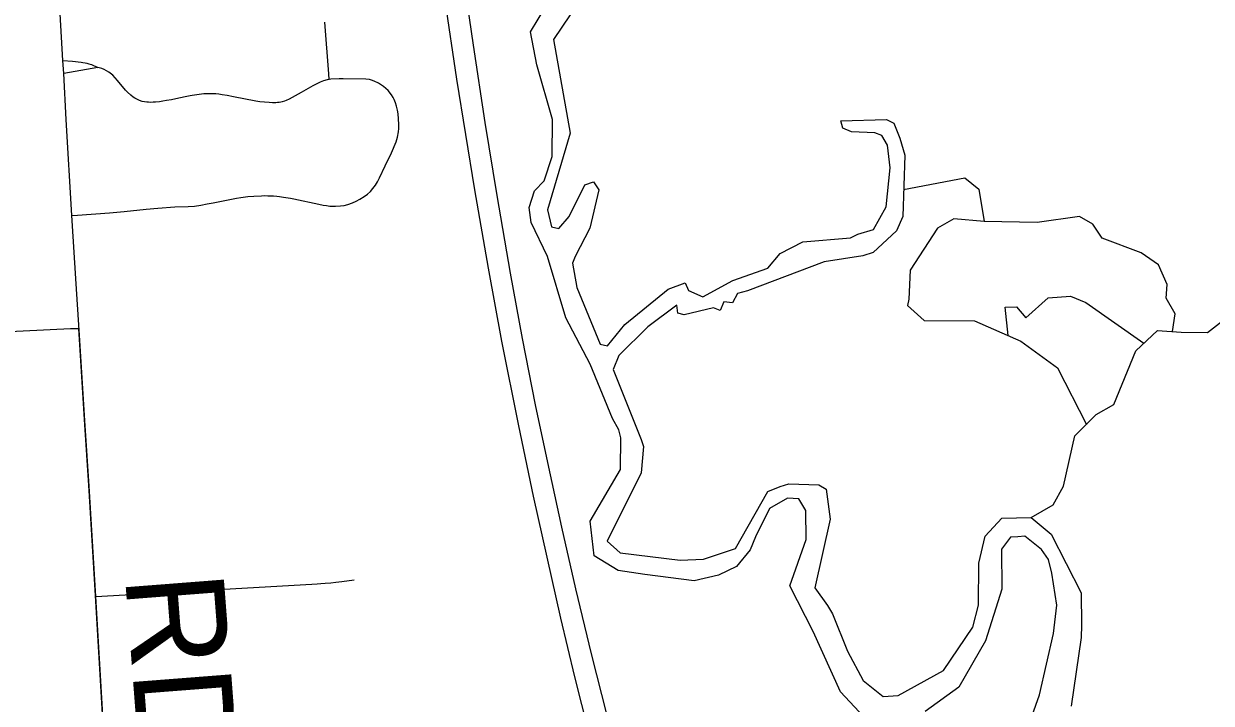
# Model space of a CAD drawing. Extents: x -6.4 to 34, y -4.2 to 22.
# Drawn here: x 3.688 to 4.373, y 19.407 to 19.8 of the extents above; entities that cross this region are included whole.
import ezdxf

# ---------------------------------------------------------------- set-up
doc = ezdxf.new("R2010")
doc.units = 0
for name, color, linetype in [('GM_X_Corporation', 7, 'Continuous'), ('GM_X_County_Road', 7, 'Continuous'), ('GM_X_County_Road_Text', 7, 'Continuous'), ('GM_X_Major_River', 7, 'Continuous'), ('GM_X_Minor_River', 7, 'Continuous'), ('GM_X_State_Route', 7, 'Continuous'), ('GM_X_Township_Road', 7, 'Continuous')]:
    doc.layers.add(name, color=color, linetype=linetype)

msp = doc.modelspace()

# ---------------------------------------------------------------- linework, layer by layer
at = {"layer": 'GM_X_Corporation'}
msp.add_lwpolyline([(3.73708, 19.33266), (3.72894, 19.4696), (3.7251, 19.53337), (3.72278, 19.56814), (3.71932, 19.62364), (3.7145, 19.62355), (3.65582, 19.62064)], dxfattribs=at)
at = {"layer": 'GM_X_County_Road'}
for points in [[(3.71955, 19.62276), (3.7178, 19.64956), (3.71545, 19.68905), (3.71217, 19.74445), (3.71066, 19.77108), (3.71023, 19.77858), (3.70647, 19.8427), (3.70137, 19.92977), (3.69885, 19.97289)], [(3.73728, 19.33211), (3.72914, 19.46905), (3.7253, 19.53281), (3.72298, 19.56759), (3.71955, 19.62276)]]:
    msp.add_lwpolyline(points, dxfattribs=at)
at = {"layer": 'GM_X_Major_River'}
for points in [[(4.17787, 19.39383), (4.15898, 19.41397), (4.14323, 19.44896), (4.1299, 19.47528), (4.13926, 19.50201), (4.13897, 19.5187), (4.13507, 19.52545), (4.12853, 19.52594), (4.11814, 19.51983), (4.10992, 19.50346), (4.10684, 19.4961), (4.09907, 19.48647), (4.08857, 19.48135), (4.07463, 19.47806), (4.04604, 19.48178), (4.03065, 19.48408), (4.01688, 19.49255), (4.01463, 19.51262), (4.03211, 19.54242), (4.03232, 19.56075), (4.0311, 19.56528), (4.02746, 19.57184), (4.01454, 19.60329), (4.00045, 19.62997), (3.98999, 19.66544), (3.98057, 19.685), (3.97928, 19.6937), (3.98251, 19.70325), (3.98802, 19.70898), (3.99265, 19.72319), (3.99275, 19.74441), (3.98387, 19.77612), (3.98013, 19.79501), (3.99335, 19.81726)], [(4.00303, 19.80492), (3.99344, 19.79071), (4.0031, 19.73663), (3.98989, 19.69238), (3.99234, 19.68256), (3.99651, 19.6815), (4.00244, 19.68844), (4.01157, 19.70681), (4.01646, 19.70842), (4.01957, 19.70393), (4.01429, 19.68182), (4.00588, 19.66535), (4.00443, 19.66154), (4.00695, 19.64754), (4.02039, 19.61478), (4.02457, 19.61372), (4.03456, 19.62605), (4.05954, 19.64661), (4.06931, 19.65021), (4.07128, 19.64569), (4.07967, 19.64205), (4.0969, 19.65147), (4.1172, 19.65867), (4.12424, 19.66715), (4.13736, 19.67384), (4.16493, 19.67624), (4.16905, 19.67822), (4.17808, 19.68104), (4.18541, 19.69407), (4.18766, 19.7165), (4.18629, 19.72975), (4.18296, 19.73517), (4.17898, 19.73683), (4.16536, 19.73733), (4.1604, 19.73952), (4.15919, 19.74367), (4.18565, 19.74454), (4.18985, 19.74234), (4.19341, 19.73368), (4.19623, 19.72386), (4.19497, 19.68856), (4.19133, 19.68014), (4.17793, 19.66776), (4.17192, 19.66575), (4.14966, 19.6623), (4.10533, 19.64556), (4.09968, 19.64393), (4.09675, 19.63857), (4.09182, 19.63924), (4.08964, 19.63426), (4.08583, 19.63571), (4.06889, 19.63161), (4.06508, 19.63268), (4.06463, 19.63722), (4.04782, 19.62477), (4.0311, 19.60815), (4.02784, 19.60012), (4.04406, 19.55982), (4.04527, 19.55567), (4.04402, 19.54047), (4.02429, 19.50103), (4.03198, 19.49435), (4.06647, 19.49005), (4.08008, 19.49068), (4.09851, 19.49671), (4.11721, 19.52968), (4.12427, 19.53257), (4.12924, 19.53407), (4.14665, 19.53363), (4.15085, 19.53105), (4.15305, 19.51364), (4.1443, 19.47402), (4.15166, 19.46392), (4.1544, 19.45903), (4.16308, 19.43753), (4.1721, 19.42066), (4.18361, 19.41139)], [(4.18361, 19.41139), (4.1923, 19.41193), (4.21852, 19.42644), (4.23548, 19.45142), (4.23866, 19.464), (4.23898, 19.48828), (4.24249, 19.5039), (4.25214, 19.51433), (4.26915, 19.51464), (4.28067, 19.50498), (4.29791, 19.47115), (4.29817, 19.45257), (4.29799, 19.44536), (4.29226, 19.4058)], [(4.26246, 19.37983), (4.27399, 19.41229), (4.28207, 19.44772), (4.28404, 19.46407), (4.28107, 19.48261), (4.27914, 19.49048), (4.27512, 19.49628), (4.26556, 19.50395), (4.26141, 19.50349), (4.25725, 19.50342), (4.25208, 19.49649), (4.25211, 19.47335), (4.2428, 19.44358), (4.22739, 19.41674), (4.20797, 19.40273)]]:
    msp.add_lwpolyline(points, dxfattribs=at)
at = {"layer": 'GM_X_Minor_River'}
for points in [[(4.19552, 19.70407), (4.23088, 19.71084), (4.23894, 19.70416), (4.24192, 19.68562)], [(4.35073, 19.62203), (4.35218, 19.63226), (4.3471, 19.64127), (4.34772, 19.64925), (4.3426, 19.66054), (4.33264, 19.66756), (4.31018, 19.67588), (4.30473, 19.68412), (4.29709, 19.68854), (4.27257, 19.68505), (4.24192, 19.68562), (4.22449, 19.6872), (4.21513, 19.68172), (4.1993, 19.65752), (4.19846, 19.64082), (4.19777, 19.63701), (4.20738, 19.62846), (4.23651, 19.62824), (4.26319, 19.61658), (4.28427, 19.60104), (4.30103, 19.56844)], [(4.25592, 19.61976), (4.25414, 19.63615), (4.26057, 19.63626), (4.26598, 19.62992), (4.27901, 19.64154), (4.29186, 19.64253), (4.30062, 19.6389), (4.33424, 19.61534)], [(4.26915, 19.51464), (4.28188, 19.52208), (4.28775, 19.53281), (4.29442, 19.56177), (4.30668, 19.57413), (4.31679, 19.58001), (4.32948, 19.61098), (4.34214, 19.62259), (4.35577, 19.6217), (4.3709, 19.6216), (4.38477, 19.6323)]]:
    msp.add_lwpolyline(points, dxfattribs=at)
at = {"layer": 'GM_X_State_Route'}
for points in [[(3.88913, 20.13155), (3.89309, 20.10206), (3.90737, 19.99262), (3.91498, 19.93476), (3.92487, 19.85634), (3.93071, 19.81323), (3.93741, 19.76774), (3.94788, 19.70395), (3.95568, 19.65863), (3.96348, 19.61647), (3.97313, 19.56769), (3.98159, 19.52692), (3.99743, 19.4566), (4.00556, 19.42276), (4.02598, 19.34202), (4.03943, 19.29261)], [(3.94128, 19.82703), (3.94701, 19.78738), (3.95372, 19.7428), (3.96077, 19.70068), (3.96847, 19.65577), (3.97535, 19.6181), (3.9829, 19.57977), (3.98994, 19.54653), (3.99798, 19.50903), (4.00602, 19.47349), (4.0152, 19.43598), (4.02422, 19.40044), (4.03536, 19.35784), (4.0441, 19.326), (4.05333, 19.29269)]]:
    msp.add_lwpolyline(points, dxfattribs=at)
at = {"layer": 'GM_X_Township_Road'}
for points in [[(3.86384, 19.76755), (3.86362, 19.77079), (3.86134, 19.80062)], [(3.71023, 19.77858), (3.7157, 19.77806), (3.7207, 19.77751), (3.72178, 19.77738), (3.72306, 19.77716), (3.72408, 19.77693), (3.72526, 19.77662), (3.72596, 19.77639), (3.72664, 19.77614), (3.73028, 19.77458)], [(3.71545, 19.68905), (3.71871, 19.68923), (3.73716, 19.69052), (3.74565, 19.69131), (3.75833, 19.69274), (3.76503, 19.69332), (3.77489, 19.69399), (3.78257, 19.69425), (3.78622, 19.6945), (3.78986, 19.69497), (3.79357, 19.69572), (3.79688, 19.69635), (3.81048, 19.69904), (3.81295, 19.69945), (3.81687, 19.69999), (3.82048, 19.70031), (3.82476, 19.70048), (3.82686, 19.70052), (3.82846, 19.7005), (3.83174, 19.70032), (3.83371, 19.70017), (3.83533, 19.70001), (3.83754, 19.69973), (3.83897, 19.69953), (3.8415, 19.69912), (3.8436, 19.69874), (3.85793, 19.6956), (3.86044, 19.69511), (3.86236, 19.69478), (3.86438, 19.69452), (3.86557, 19.69443), (3.86762, 19.69438), (3.87036, 19.69457), (3.8726, 19.69492), (3.87469, 19.6954), (3.8773, 19.69627), (3.87944, 19.69725), (3.88155, 19.69841), (3.8842, 19.70004), (3.88598, 19.70135), (3.88771, 19.70296), (3.88919, 19.70455), (3.89068, 19.70657), (3.89176, 19.7084), (3.89293, 19.71074), (3.89632, 19.71769), (3.89984, 19.7252), (3.90255, 19.73154), (3.90332, 19.73423), (3.9039, 19.73726), (3.90405, 19.73923), (3.90413, 19.74154), (3.90395, 19.74484), (3.90365, 19.74783), (3.9033, 19.74996), (3.9028, 19.75225), (3.90222, 19.75403), (3.90139, 19.75605), (3.90076, 19.75726), (3.89988, 19.75867), (3.89794, 19.76116), (3.89533, 19.76354), (3.89229, 19.76552), (3.88988, 19.76665), (3.8884, 19.76724), (3.88711, 19.76758), (3.88516, 19.76781), (3.87196, 19.768), (3.8696, 19.768), (3.8649, 19.76774), (3.86384, 19.76755), (3.86284, 19.76738), (3.86072, 19.76679), (3.85868, 19.76602), (3.85451, 19.76397), (3.84766, 19.75999), (3.84073, 19.75619), (3.83912, 19.7555), (3.8381, 19.75511), (3.83687, 19.75471), (3.83597, 19.75449), (3.83499, 19.75431), (3.83411, 19.75421), (3.83308, 19.75415), (3.83184, 19.7541), (3.83118, 19.7541), (3.82931, 19.7542), (3.82397, 19.75468), (3.82156, 19.75501), (3.80871, 19.75761), (3.80501, 19.75834), (3.80223, 19.75878), (3.80013, 19.75905), (3.79847, 19.7592), (3.79645, 19.7593), (3.79403, 19.75932), (3.79158, 19.75922), (3.78888, 19.75894), (3.78476, 19.75838), (3.78369, 19.7582), (3.78088, 19.75763), (3.77533, 19.7564), (3.77295, 19.75592), (3.76999, 19.75536), (3.76788, 19.75502), (3.76593, 19.75477), (3.76367, 19.75453), (3.76225, 19.75443), (3.7606, 19.75438), (3.75969, 19.75441), (3.75872, 19.75448), (3.75738, 19.75464), (3.75602, 19.75494), (3.75451, 19.75538), (3.75319, 19.75595), (3.75177, 19.75671), (3.7507, 19.75744), (3.74935, 19.75853), (3.74755, 19.76024), (3.74637, 19.76149), (3.74176, 19.7669), (3.74038, 19.76846), (3.73897, 19.76998), (3.73746, 19.77131), (3.73673, 19.77186), (3.73547, 19.77266), (3.7341, 19.77332), (3.73272, 19.77387), (3.73028, 19.77458), (3.71066, 19.77108)], [(3.72914, 19.46905), (3.85394, 19.47614), (3.85694, 19.47634), (3.85911, 19.47651), (3.86157, 19.47673), (3.86487, 19.47705), (3.86773, 19.47735), (3.87116, 19.47775), (3.87832, 19.47867)]]:
    msp.add_lwpolyline(points, dxfattribs=at)

# ---------------------------------------------------------------- texts
at = {"layer": 'GM_X_County_Road_Text'}
msp.add_text('RD', height=0.056818, rotation=274.43596, dxfattribs=at).set_placement((3.74602, 19.48067))

doc.saveas('drawing.dxf')
